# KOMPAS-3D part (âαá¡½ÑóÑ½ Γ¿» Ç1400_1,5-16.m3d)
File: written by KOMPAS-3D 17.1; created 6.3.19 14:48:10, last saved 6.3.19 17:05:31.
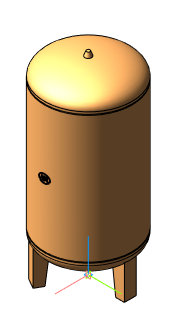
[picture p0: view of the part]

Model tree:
1. Операция без истории:1  (with: Сечение модели:1)

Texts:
  Гранлевел тип А100_1,5-16
  Гранлевел тип А150_1,5-16
  Гранлевел тип А220_1,5-16
  Гранлевел тип А350_1,5-16
  Гранлевел тип А500_1,5-16
  Гранлевел тип А700_1,5-16
  Гранлевел тип А900_1,5-16
  Гранлевел тип А1000_1,5-16
  Гранлевел тип А1400_1,5-16
  Точка начала. Х
  Точка начала. Y
  Точка начала. Z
